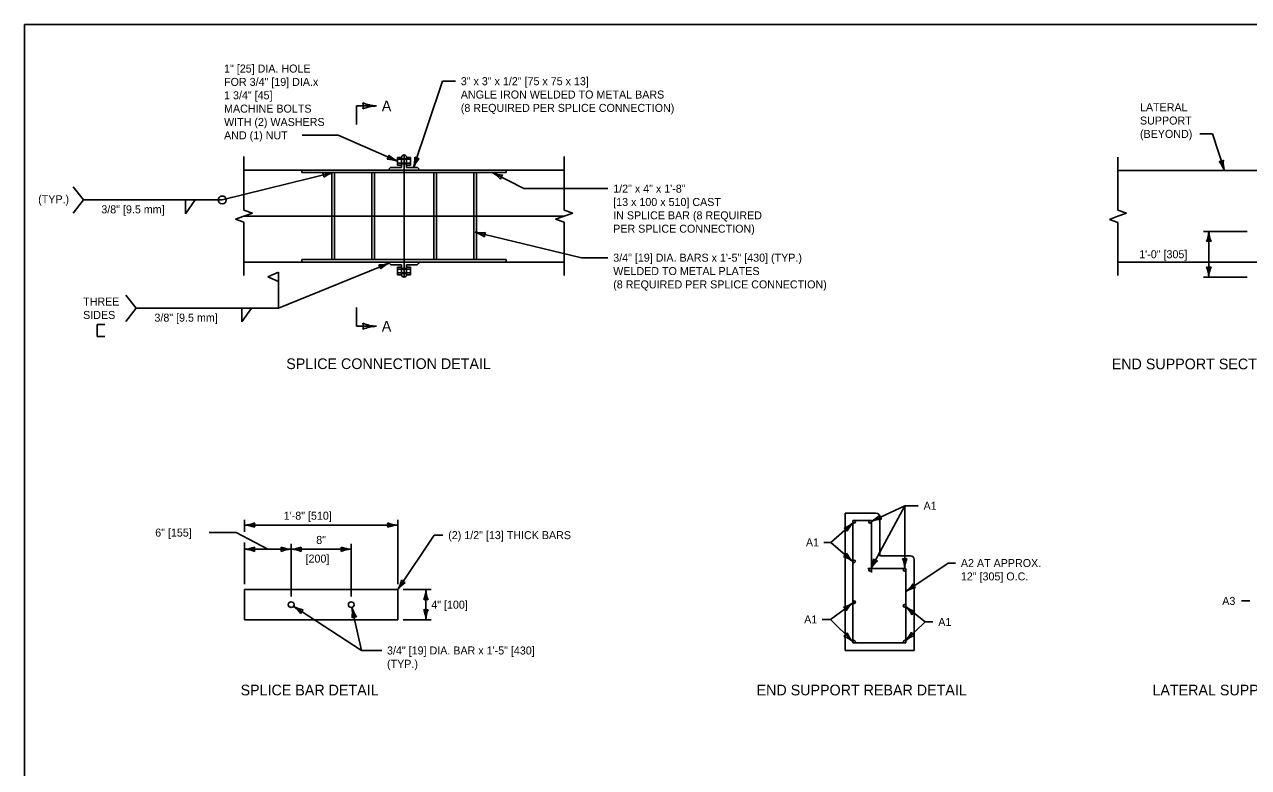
# Model space of a CAD drawing. Extents: x 49987.2 to 50044, y 49982.5 to 50011.4.
# Drawn here: x 49999.38 to 50008.56, y 49993.43 to 49999 of the extents above; entities that cross this region are included whole.
import ezdxf

# ---------------------------------------------------------------- set-up
doc = ezdxf.new("R2010")
doc.units = 0
for name, color, linetype in [('Level 1', 7, 'Continuous'), ('Level 2', 7, 'Continuous'), ('Level 3', 7, 'Continuous'), ('Level 4', 7, 'Continuous'), ('Level 5', 7, 'Continuous'), ('Level 6', 7, 'Continuous'), ('P_Template_Detour_Alignment_Urban_Text', 7, 'Continuous')]:
    doc.layers.add(name, color=color, linetype=linetype)

msp = doc.modelspace()

# ---------------------------------------------------------------- linework, layer by layer
at = {"layer": 'Level 1'}
for p, q in [((50002.1789, 49997.9469), (50002.1789, 49998.0039)), ((50002.1789, 49998.0039), (50002.2089, 49998.0039)), ((50002.2779, 49997.9897), (50002.1789, 49997.9897)), ((50002.2089, 49998.0039), (50002.2089, 49997.9289)), ((50002.2284, 49998.0219), (50002.2284, 49997.8899)), ((50002.2779, 49998.0039), (50002.2479, 49998.0039)), ((50002.2479, 49998.0039), (50002.2479, 49997.9289)), ((50002.2779, 49997.9469), (50002.2779, 49998.0039)), ((50003.4285, 49997.9094), (50001.0285, 49997.9094)), ((50001.4634, 49997.8899), (50001.4634, 49997.9094)), ((50002.1354, 49997.9289), (50002.2089, 49997.9289)), ((50002.2779, 49997.9612), (50002.1789, 49997.9612)), ((50002.2089, 49997.9469), (50002.1789, 49997.9469)), ((50002.2479, 49997.9469), (50002.2779, 49997.9469)), ((50002.3214, 49997.9289), (50002.2479, 49997.9289)), ((50002.9934, 49997.8899), (50002.9934, 49997.9094)), ((50007.5791, 49997.9057), (50009.174, 49997.9057)), ((50001.4634, 49997.8899), (50002.9934, 49997.8899)), ((50001.6859, 49997.2389), (50001.6859, 49997.8899)), ((50001.7059, 49997.2389), (50001.7059, 49997.8899)), ((50001.9859, 49997.2389), (50001.9859, 49997.8899)), ((50002.0059, 49997.2389), (50002.0059, 49997.8899)), ((50002.2284, 49997.2389), (50002.2284, 49997.8899)), ((50002.4509, 49997.2389), (50002.4509, 49997.8899)), ((50002.4709, 49997.2389), (50002.4709, 49997.8899)), ((50002.7509, 49997.2389), (50002.7509, 49997.8899)), ((50002.7709, 49997.2389), (50002.7709, 49997.8899)), ((50001.0286, 49997.5644), (50003.4286, 49997.5644)), ((50001.0285, 49997.2194), (50003.4285, 49997.2194)), ((50002.9934, 49997.2389), (50001.4634, 49997.2389)), ((50001.4634, 49997.2389), (50001.4634, 49997.2194)), ((50002.1354, 49997.1999), (50002.2089, 49997.1999)), ((50002.2089, 49997.1819), (50002.1789, 49997.1819)), ((50002.1789, 49997.1819), (50002.1789, 49997.1249)), ((50002.1789, 49997.1677), (50002.2779, 49997.1677)), ((50002.2089, 49997.1249), (50002.2089, 49997.1999)), ((50002.2284, 49997.2389), (50002.2284, 49997.1069)), ((50002.3214, 49997.1999), (50002.2479, 49997.1999)), ((50002.2479, 49997.1249), (50002.2479, 49997.1999)), ((50002.2479, 49997.1819), (50002.2779, 49997.1819)), ((50002.2779, 49997.1819), (50002.2779, 49997.1249)), ((50002.9934, 49997.2389), (50002.9934, 49997.2194)), ((50007.5791, 49997.2194), (50008.6565, 49997.2194)), ((50002.1789, 49997.1392), (50002.2779, 49997.1392)), ((50002.1789, 49997.1249), (50002.2089, 49997.1249)), ((50002.2779, 49997.1249), (50002.2479, 49997.1249)), ((50005.5346, 49994.3108), (50005.5346, 49995.3402)), ((50005.5346, 49995.3402), (50005.7652, 49995.3402)), ((50005.7315, 49995.2839), (50005.5908, 49995.2839)), ((50005.5908, 49995.2839), (50005.5908, 49994.367)), ((50005.7315, 49994.8958), (50005.7315, 49995.2839)), ((50005.7934, 49995.3121), (50005.7934, 49995.0196)), ((50005.7934, 49995.0196), (50006.024, 49995.0196)), ((50006.0521, 49994.9914), (50006.0521, 49994.3108)), ((50005.9902, 49994.9239), (50005.7034, 49994.9239)), ((50005.9902, 49994.367), (50005.9902, 49994.9239)), ((50002.1811, 49994.7664), (50001.0336, 49994.7664)), ((50001.0336, 49994.7664), (50001.0336, 49994.5414)), ((50002.1811, 49994.5414), (50002.1811, 49994.7664)), ((50001.0336, 49994.5414), (50002.1811, 49994.5414)), ((50005.5908, 49994.367), (50005.9902, 49994.367)), ((50006.0521, 49994.3108), (50005.5346, 49994.3108))]:
    msp.add_line(p, q, dxfattribs=at)
msp.add_lwpolyline([(49999.3835, 49998.9992), (50016.7501, 49998.9992), (50016.7501, 49987.7988), (49999.3835, 49987.7988)], close=True, dxfattribs=at)
for centre, radius in [((50005.6008, 49995.2739), 0.01), ((50005.7215, 49995.2739), 0.01), ((50005.6008, 49994.9783), 0.01), ((50005.7215, 49994.9139), 0.01), ((50005.9802, 49994.9139), 0.01), ((50005.6008, 49994.6727), 0.01), ((50001.3823, 49994.6539), 0.0214), ((50001.8323, 49994.6539), 0.0214), ((50005.9802, 49994.6455), 0.01), ((50005.6008, 49994.377), 0.01), ((50005.9802, 49994.377), 0.01)]:
    msp.add_circle(centre, radius, dxfattribs=at)
for centre, radius, start, end in [((50002.2284, 49998.0024), 0.0196, 4.58122, 175.41878), ((50002.1354, 49997.9094), 0.0195, 90, 180), ((50002.3214, 49997.9094), 0.0195, 0, 90), ((50002.1354, 49997.2194), 0.0195, 180, 270), ((50002.3214, 49997.2194), 0.0195, 270, 0), ((50002.2284, 49997.1265), 0.0196, 184.58122, 355.41878), ((50005.7652, 49995.3121), 0.0281, 0, 90), ((50006.024, 49994.9914), 0.0281, 0, 90)]:
    msp.add_arc(centre, radius, start, end, dxfattribs=at)
at = {"layer": 'Level 2'}
for p, q in [((49999.9867, 49996.7518), (49999.9284, 49996.7518)), ((49999.9284, 49996.7518), (49999.9284, 49996.6623)), ((49999.9867, 49996.6623), (49999.9284, 49996.6623))]:
    msp.add_line(p, q, dxfattribs=at)
at = {"layer": 'Level 3'}
for p, q in [((50002.3004, 49997.9289), (50002.5154, 49998.5746)), ((50002.5154, 49998.5746), (50002.6137, 49998.5746)), ((50001.7351, 49998.1692), (50001.4643, 49998.1692)), ((50002.1789, 49997.9754), (50001.7351, 49998.1692)), ((50008.2875, 49998.1798), (50008.1924, 49998.1798)), ((50008.3766, 49997.9057), (50008.2875, 49998.1798)), ((50001.6959, 49997.8899), (50000.8654, 49997.6849)), ((50002.8925, 49997.8899), (50003.1262, 49997.7698)), ((49999.8264, 49997.6849), (49999.7483, 49997.7826)), ((50003.1262, 49997.7698), (50003.7561, 49997.7698)), ((49999.8264, 49997.6849), (49999.7483, 49997.5872)), ((50000.8654, 49997.6849), (49999.8264, 49997.6849)), ((50000.5905, 49997.6849), (50000.5905, 49997.5824)), ((50000.5905, 49997.5824), (50000.6638, 49997.6849)), ((50002.7609, 49997.4432), (50003.5596, 49997.2527)), ((50008.2597, 49997.45), (50008.2597, 49997.1069)), ((50003.5596, 49997.2527), (50003.7561, 49997.2527)), ((50002.1171, 49997.2126), (50001.2864, 49996.8737)), ((50001.2864, 49996.8737), (50001.2864, 49997.1438)), ((50000.2204, 49996.8737), (50000.1423, 49996.9713)), ((50000.2204, 49996.8737), (50000.1423, 49996.776)), ((50001.2864, 49996.8737), (50000.2204, 49996.8737)), ((50001.0116, 49996.8737), (50001.0116, 49996.7711)), ((50001.0116, 49996.7711), (50001.0848, 49996.8737)), ((50005.7262, 49994.9227), (50005.9817, 49995.3947)), ((50005.7305, 49995.2781), (50005.9817, 49995.3947)), ((50005.9806, 49994.9239), (50005.9817, 49995.3947)), ((50005.9817, 49995.3947), (50006.0822, 49995.3947)), ((50001.0336, 49995.2004), (50001.0336, 49995.2902)), ((50001.0336, 49995.2502), (50002.1811, 49995.2502)), ((50002.1811, 49994.8064), (50002.1811, 49995.2902)), ((50005.5934, 49995.2673), (50005.4275, 49995.1199)), ((50002.1811, 49994.7664), (50002.4531, 49995.1748)), ((50002.4531, 49995.1748), (50002.5194, 49995.1748)), ((50001.0336, 49994.8064), (50001.0336, 49995.1204)), ((50001.0336, 49995.0689), (50001.3823, 49995.0689)), ((50001.3823, 49994.7153), (50001.3823, 49995.1089)), ((50001.3823, 49995.0689), (50001.8323, 49995.0689)), ((50001.8323, 49994.7153), (50001.8323, 49995.1089)), ((50005.4275, 49995.1199), (50005.375, 49995.1199)), ((50005.5908, 49994.9783), (50005.4275, 49995.1199)), ((50005.9902, 49994.753), (50006.3074, 49994.9656)), ((50006.3074, 49994.9656), (50006.3616, 49994.9656)), ((50002.2211, 49994.7664), (50002.4325, 49994.7664)), ((50002.3925, 49994.7664), (50002.3925, 49994.5414)), ((50001.9093, 49994.3108), (50001.4003, 49994.6423)), ((50001.9093, 49994.3108), (50001.837, 49994.6331)), ((50005.6008, 49994.6727), (50005.4236, 49994.5433)), ((50005.9881, 49994.6393), (50006.1339, 49994.5244)), ((50008.5685, 49994.682), (50008.5063, 49994.682)), ((50002.2211, 49994.5414), (50002.4325, 49994.5414)), ((50005.4236, 49994.5433), (50005.362, 49994.5433)), ((50005.5908, 49994.377), (50005.4236, 49994.5433)), ((50005.9873, 49994.3841), (50006.1339, 49994.5244)), ((50006.1339, 49994.5244), (50006.1925, 49994.5244)), ((50001.9093, 49994.3108), (50002.0608, 49994.3108))]:
    msp.add_line(p, q, dxfattribs=at)
msp.add_lwpolyline([(50001.208, 49995.0689), (50000.9702, 49995.1937), (50000.7684, 49995.1937)], dxfattribs=at)
msp.add_circle((50000.8654, 49997.6849), 0.0297, dxfattribs=at)
for centre, radius, start, end in [((50001.8505, 49998.3895), 0.073, 342.13882, 17.86118), ((50002.0368, 49998.6997), 0.3107, 247.92284, 267.17269), ((50002.0337, 49998.0933), 0.2964, 92.36048, 112.54399), ((50002.0614, 49998.0267), 0.0548, 318.55258, 354.27494), ((50002.0963, 49997.7575), 0.233, 69.24107, 88.49092), ((50002.2762, 49998.1753), 0.2223, 223.86977, 244.05328), ((50002.076, 49997.9915), 0.233, 344.41242, 3.66227), ((50002.5083, 49997.8501), 0.2223, 139.04112, 159.22462), ((50002.3409, 49998.0506), 0.0548, 233.72393, 269.44629), ((50008.337, 49998.0276), 0.0548, 270.14873, 305.87109), ((50008.1588, 49997.8228), 0.233, 20.83722, 40.08707), ((50008.5907, 49997.9657), 0.2223, 175.46592, 195.64943), ((50001.6515, 49998.1078), 0.2223, 261.32127, 281.50478), ((50001.5714, 49997.8592), 0.0548, 356.00408, 31.72644), ((50001.7628, 49997.6667), 0.233, 106.69257, 125.94242), ((50002.7828, 49997.6965), 0.2223, 40.25133, 60.43484), ((50002.9887, 49998.1021), 0.233, 245.62263, 264.87248), ((50003.0066, 49997.8313), 0.0548, 134.93414, 170.6565), ((50002.7004, 49997.2293), 0.2223, 54.04148, 74.22499), ((50002.8037, 49997.6723), 0.233, 259.41278, 278.66263), ((50002.8856, 49997.4135), 0.0548, 148.72429, 184.44665), ((50008.0376, 49997.4592), 0.2223, 337.45601, 357.63952), ((50008.4925, 49997.4615), 0.233, 182.82731, 202.07716), ((50008.2597, 49997.3218), 0.0548, 72.13882, 107.86118), ((50002.0417, 49997.4217), 0.2223, 269.65268, 289.83619), ((50001.9984, 49997.1642), 0.0548, 4.33549, 40.05785), ((50002.2157, 49997.0015), 0.233, 115.02398, 134.27383), ((50008.2597, 49997.2351), 0.0548, 252.13882, 287.86118), ((50008.027, 49997.0954), 0.233, 2.82731, 22.07716), ((50008.4819, 49997.0978), 0.2223, 157.45601, 177.63952), ((50002.0337, 49997.0355), 0.2964, 247.45601, 267.63952), ((50001.8505, 49996.7394), 0.073, 342.13882, 17.86118), ((50002.0368, 49996.4291), 0.3107, 92.82731, 112.07716), ((50005.6238, 49995.4852), 0.233, 297.27026, 316.52011), ((50005.8473, 49995.3312), 0.0548, 186.58176, 222.30412), ((50001.0221, 49995.4829), 0.233, 272.82731, 292.07716), ((50001.0244, 49995.0281), 0.2223, 67.45601, 87.63952), ((50001.1618, 49995.2502), 0.0548, 162.13882, 197.86118), ((50002.1902, 49995.4723), 0.2223, 247.45601, 267.63952), ((50002.0529, 49995.2502), 0.0548, 342.13882, 17.86118), ((50002.1926, 49995.0175), 0.233, 92.82731, 112.07716), ((50005.4494, 49995.4367), 0.2223, 290.17436, 310.35787), ((50005.7597, 49995.1041), 0.233, 135.54566, 154.79551), ((50005.8141, 49995.0721), 0.2223, 91.89896, 112.08246), ((50005.4992, 49995.1803), 0.0548, 24.85717, 60.57953), ((50001.0221, 49995.3016), 0.233, 272.82731, 292.07716), ((50001.0244, 49994.8467), 0.2223, 67.45601, 87.63952), ((50001.1618, 49995.0689), 0.0548, 162.13882, 197.86118), ((50001.3915, 49995.291), 0.2223, 247.45601, 267.63952), ((50001.2541, 49995.0689), 0.0548, 342.13882, 17.86118), ((50001.3938, 49994.8362), 0.233, 92.82731, 112.07716), ((50001.3709, 49995.3016), 0.233, 272.82731, 292.07716), ((50001.3732, 49994.8467), 0.2223, 67.45601, 87.63952), ((50001.5106, 49995.0689), 0.0548, 162.13882, 197.86118), ((50001.8415, 49995.291), 0.2223, 247.45601, 267.63952), ((50001.7041, 49995.0689), 0.0548, 342.13882, 17.86118), ((50001.8438, 49994.8362), 0.233, 92.82731, 112.07716), ((50005.494, 49995.0623), 0.0548, 301.21695, 336.93931), ((50005.4471, 49994.7949), 0.233, 51.90544, 71.15529), ((50005.7433, 49995.1401), 0.2223, 206.53414, 226.71765), ((50005.5146, 49995.0202), 0.233, 335.25837, 354.50822), ((50005.9189, 49994.8118), 0.2223, 129.88707, 150.07057), ((50005.7856, 49995.0364), 0.0548, 224.56987, 260.29224), ((50005.9809, 49995.0521), 0.0548, 252.01259, 287.73495), ((50005.7479, 49994.9129), 0.233, 2.70108, 21.95093), ((50006.2027, 49994.9143), 0.2223, 157.32978, 177.51329), ((50001.981, 49994.8859), 0.233, 329.15817, 348.40802), ((50002.3609, 49994.6356), 0.2223, 123.78687, 143.97038), ((50002.2522, 49994.8731), 0.0548, 218.46968, 254.19204), ((50005.8511, 49994.9399), 0.233, 306.6581, 325.90795), ((50006.1063, 49994.5634), 0.2223, 101.2868, 121.47031), ((50006.0967, 49994.8244), 0.0548, 195.96961, 231.69197), ((50002.1703, 49994.7756), 0.2223, 337.45601, 357.63952), ((50002.3925, 49994.6382), 0.0548, 72.13882, 107.86118), ((50002.6252, 49994.7779), 0.233, 182.82731, 202.07716), ((50001.2727, 49994.4602), 0.2223, 34.80515, 54.98866), ((50001.5161, 49994.8444), 0.233, 240.17645, 259.4263), ((50001.5082, 49994.5731), 0.0548, 129.48796, 165.21032), ((50001.6189, 49994.5903), 0.2223, 350.90823, 11.09174), ((50002.0607, 49994.6984), 0.233, 196.27953, 215.52938), ((50002.3925, 49994.6696), 0.0548, 252.13882, 287.86118), ((50002.1598, 49994.5299), 0.233, 2.82731, 22.07716), ((50002.6146, 49994.5323), 0.2223, 157.45601, 177.63952), ((50005.4688, 49994.8513), 0.2223, 283.71627, 303.89977), ((50005.4894, 49994.5909), 0.0548, 18.39907, 54.12143), ((50005.7397, 49994.4859), 0.233, 129.08757, 148.33742), ((50005.8379, 49994.4753), 0.2223, 27.32763, 47.51114), ((50006.1293, 49994.8246), 0.233, 232.69893, 251.94878), ((50006.0861, 49994.5567), 0.0548, 122.01044, 157.7328), ((50001.8668, 49994.5084), 0.0548, 85.59104, 121.3134), ((50005.4999, 49994.4674), 0.0548, 297.3059, 333.02826), ((50005.4349, 49994.2039), 0.233, 47.99439, 67.24424), ((50005.754, 49994.5281), 0.2223, 202.62309, 222.8066), ((50005.8181, 49994.5443), 0.233, 316.57371, 335.82356), ((50006.1343, 49994.2173), 0.2223, 111.20241, 131.38591), ((50006.0799, 49994.4728), 0.0548, 205.88521, 241.60757)]:
    msp.add_arc(centre, radius, start, end, dxfattribs=at)
at = {"layer": 'Level 4'}
for p, q in [((50002.2479, 49997.9942), (50002.2089, 49997.9942)), ((50002.2479, 49997.9567), (50002.2089, 49997.9567)), ((50002.2089, 49997.1722), (50002.2479, 49997.1722)), ((50002.2089, 49997.1347), (50002.2479, 49997.1347))]:
    msp.add_line(p, q, dxfattribs=at)
at = {"layer": 'Level 5'}
for p, q in [((50008.5468, 49997.45), (50008.2197, 49997.45)), ((50008.5468, 49997.1069), (50008.2197, 49997.1069))]:
    msp.add_line(p, q, dxfattribs=at)
at = {"layer": 'Level 6'}
for p, q in [((50002.0215, 49998.3895), (50001.8715, 49998.3895)), ((50001.8715, 49998.3895), (50001.8715, 49998.2495)), ((50001.0285, 49998.0094), (50001.0285, 49997.6098)), ((50003.4285, 49998.0094), (50003.4285, 49997.6098)), ((50007.5791, 49998.0057), (50007.5791, 49997.608)), ((50001.0285, 49997.5644), (50000.9645, 49997.5417)), ((50001.0285, 49997.519), (50000.9645, 49997.5417)), ((50001.0925, 49997.5871), (50001.0285, 49997.6098)), ((50001.0925, 49997.5871), (50001.0285, 49997.5644)), ((50003.4285, 49997.5644), (50003.3645, 49997.5417)), ((50003.4285, 49997.519), (50003.3645, 49997.5417)), ((50003.4925, 49997.5871), (50003.4285, 49997.6098)), ((50003.4925, 49997.5871), (50003.4285, 49997.5644)), ((50007.5791, 49997.5626), (50007.5151, 49997.5399)), ((50007.5791, 49997.5172), (50007.5151, 49997.5399)), ((50007.6431, 49997.5853), (50007.5791, 49997.608)), ((50007.6431, 49997.5853), (50007.5791, 49997.5626)), ((50001.0285, 49997.519), (50001.0285, 49997.1194)), ((50003.4285, 49997.519), (50003.4285, 49997.1194)), ((50007.5791, 49997.5172), (50007.5791, 49997.1194)), ((50001.8715, 49996.7394), (50001.8715, 49996.8794)), ((50002.0215, 49996.7394), (50001.8715, 49996.7394))]:
    msp.add_line(p, q, dxfattribs=at)
at = {"layer": 'P_Template_Detour_Alignment_Urban_Text'}
for p, q in [((50001.2864, 49997.1438), (50001.2065, 49997.1086)), ((50001.2065, 49997.1086), (50001.2864, 49997.0734)), ((50001.2864, 49997.1438), (50001.2864, 49996.8765)), ((50001.2864, 49996.8765), (50001.2864, 49997.1438))]:
    msp.add_line(p, q, dxfattribs=at)

# ---------------------------------------------------------------- texts
at = {"layer": 'Level 2'}
for s, height, p in [('1" [25] DIA. HOLE', 0.06, (50000.8794, 49998.6392)), ('FOR 3/4" [19] DIA.x', 0.06, (50000.8794, 49998.5392)), ('3" x 3" x 1/2" [75 x 75 x 13]', 0.06, (50002.6537, 49998.5446)), ('1 3/4" [45]', 0.06, (50000.8794, 49998.4392)), ('ANGLE IRON WELDED TO METAL BARS', 0.06, (50002.6537, 49998.4446)), ('MACHINE BOLTS', 0.06, (50000.8794, 49998.3392)), ('A', 0.08, (50002.0615, 49998.3495)), ('(8 REQUIRED PER SPLICE CONNECTION)', 0.06, (50002.6537, 49998.3446)), ('LATERAL', 0.06, (50007.7441, 49998.3498)), ('WITH (2) WASHERS', 0.06, (50000.8794, 49998.2392)), ('SUPPORT', 0.06, (50007.7441, 49998.2498)), ('AND (1) NUT', 0.06, (50000.8794, 49998.1392)), ('(BEYOND)', 0.06, (50007.7441, 49998.1498)), ('1/2" x 4" x 1\'-8"', 0.06, (50003.7961, 49997.7398)), ('(TYP.)', 0.06, (49999.4861, 49997.6605)), ('3/8" [9.5 mm]', 0.06, (49999.9593, 49997.5849)), ('[13 x 100 x 510] CAST', 0.06, (50003.7961, 49997.6398)), ('IN SPLICE BAR (8 REQUIRED', 0.06, (50003.7961, 49997.5398)), ('PER SPLICE CONNECTION)', 0.06, (50003.7961, 49997.4398)), ('3/4" [19] DIA. BARS x 1\'-5" [430] (TYP.)', 0.06, (50003.7961, 49997.2227)), ('1\'-0" [305]', 0.06, (50007.7385, 49997.2485)), ('WELDED TO METAL PLATES', 0.06, (50003.7961, 49997.1227)), ('(8 REQUIRED PER SPLICE CONNECTION)', 0.06, (50003.7961, 49997.0227)), ('THREE', 0.06, (49999.8232, 49996.8939)), ('SIDES', 0.06, (49999.8232, 49996.7939)), ('3/8" [9.5 mm]', 0.06, (50000.3576, 49996.7737)), ('A', 0.08, (50002.0615, 49996.6994)), ('SPLICE CONNECTION DETAIL', 0.08, (50001.3457, 49996.4186)), ('END SUPPORT SECTION A-A', 0.08, (50007.5325, 49996.4168)), ('A1', 0.06, (50006.1222, 49995.3647)), ('1\'-8" [510]', 0.06, (50001.3265, 49995.2902)), ('6" [155]', 0.06, (50000.3634, 49995.1637)), ('8"', 0.06, (50001.5701, 49995.1089)), ('(2) 1/2" [13] THICK BARS', 0.06, (50002.5594, 49995.1448)), ('A1', 0.06, (50005.2405, 49995.0899)), ('[200]', 0.06, (50001.4902, 49994.9689)), ('A2 AT APPROX. ', 0.06, (50006.4017, 49994.9357)), ('12" [305] O.C.', 0.06, (50006.4017, 49994.8357)), ('4" [100]', 0.06, (50002.4325, 49994.6239)), ('A3', 0.06, (50008.3609, 49994.652)), ('A1', 0.06, (50005.2275, 49994.5133)), ('A1', 0.06, (50006.2325, 49994.4944)), ('3/4" [19] DIA. BAR x 1\'-5" [430]', 0.06, (50002.1008, 49994.2809)), ('(TYP.)', 0.06, (50002.1008, 49994.1809)), ('SPLICE BAR DETAIL', 0.08, (50001.0032, 49993.9747)), ('END SUPPORT REBAR DETAIL', 0.08, (50004.8707, 49993.9747)), ('LATERAL SUPPORT REBAR DETAIL', 0.08, (50007.8378, 49993.9747))]:
    msp.add_text(s, height=height, dxfattribs=at).set_placement(p)

doc.saveas('drawing.dxf')
